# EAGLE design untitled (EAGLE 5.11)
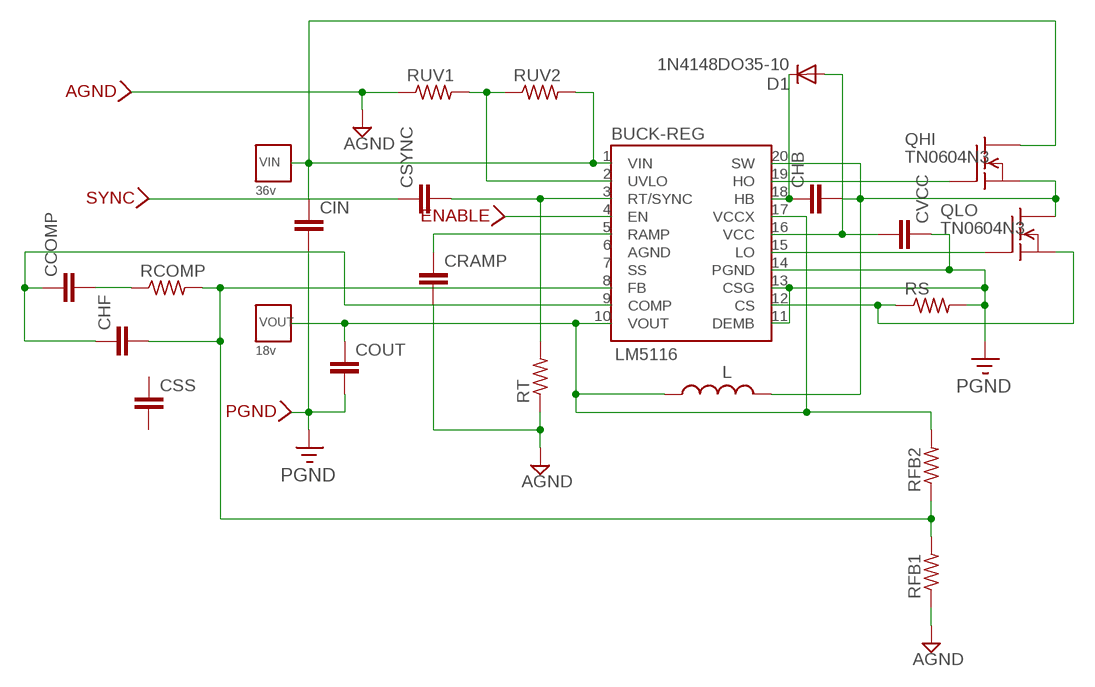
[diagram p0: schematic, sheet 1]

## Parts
AGND  WIREPAD-SMD-SMALL-NAMED  [WIREPAD-SMD-SMALL]
BUCK-REG  LM5116  [TSSOP20-POWERPAD]
CCOMP  C-EUC0805  [C0805]
CHB  C-EUC0805  [C0805]
CHF  C-EUC0805  [C0805]
CIN  C-EUC0805  [C0805]
COUT  C-EUC0805  [C0805]
CRAMP  C-EUC0805  [C0805]
CSS  C-EUC0805  [C0805]
CSYNC  C-EUC0805  [C0805]
CVCC  C-EUC0805  [C0805]
D1  1N4148DO35-10  [DO35-10]
ENABLE  WIREPAD-SMD-SMALL-NAMED  [WIREPAD-SMD-SMALL]
L  INDUCTOR  [INDUCTOR-ABRACON-1306S]
PGND  WIREPAD-SMD-SMALL-NAMED  [WIREPAD-SMD-SMALL]
QHI  TN0604N3  [TO-92]
QLO  TN0604N3  [TO-92]
RCOMP  R-US_R0805  [R0805]
RFB1  R-US_R0805  [R0805]
RFB2  R-US_R0805  [R0805]
RS  R-US_R0805  [R0805]
RT  R-US_R0805  [R0805]
RUV1  R-US_R0805  [R0805]
RUV2  R-US_R0805  [R0805]
SYNC  WIREPAD-SMD-SMALL-NAMED  [WIREPAD-SMD-SMALL]
VIN  36v  WIREPAD-SMD5X5MM  [WIREPAD-SMD-5X5MM]
VOUT  18v  WIREPAD-SMD5X5MM  [WIREPAD-SMD-5X5MM]

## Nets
AGND: AGND.1 CRAMP.2 RFB1.1 RT.1 RUV1.1
N$1: CSYNC.1 SYNC.1
N$2: BUCK-REG.5(RAMP) CRAMP.1
N$3: BUCK-REG.8(FB) CHF.2 RCOMP.2 RFB1.2 RFB2.1
N$4: BUCK-REG.1(VIN) CIN.1 QHI.3(D) RUV2.2 VIN.1(P)
N$5: BUCK-REG.2(UVLO) RUV1.2 RUV2.1
N$6: BUCK-REG.3(RT/SYNC) CSYNC.2 RT.2
N$7: BUCK-REG.4(EN) ENABLE.1
N$8: BUCK-REG.9(COMP) CCOMP.1 CHF.1
N$9: BUCK-REG.10(VOUT) BUCK-REG.17(VCCX) COUT.1 L.1 RFB2.2 VOUT.1(P)
N$10: CCOMP.2 RCOMP.1
N$11: BUCK-REG.19(HO) QHI.2(G)
N$12: BUCK-REG.20(SW) CHB.2 L.2 QHI.1(S) QLO.3(D)
N$13: BUCK-REG.18(HB) CHB.1 D1.C
N$14: BUCK-REG.12(CS) QLO.1(S) RS.1
N$15: BUCK-REG.16(VCC) CVCC.2 D1.A
N$16: BUCK-REG.15(LO) QLO.2(G)
PGND: BUCK-REG.11(DEMB) BUCK-REG.13(CSG) BUCK-REG.14(PGND) CIN.2 COUT.2 CVCC.1 PGND.1 RS.2
Unconnected: BUCK-REG.6(AGND) BUCK-REG.7(SS) CSS.1 CSS.2

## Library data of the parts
AGND ENABLE PGND SYNC = trl:WIREPAD-SMD-SMALL-NAMED
BUCK-REG = trl:LM5116
CCOMP CHB CHF CIN COUT CRAMP CSS CSYNC CVCC = rcl:C-EU: CAPACITOR, European symbol
D1 = diode:1N4148: DIODE
L = trl:INDUCTOR
QHI QLO = transistor-fet:TN0604N3: N-Channel Enhancement MOSFET 40V; 4A; 0,75Ohm
RCOMP RFB1 RFB2 RS RT RUV1 RUV2 = resistor:R-US_: RESISTOR, American symbol
VIN VOUT = trl:WIREPAD-SMD

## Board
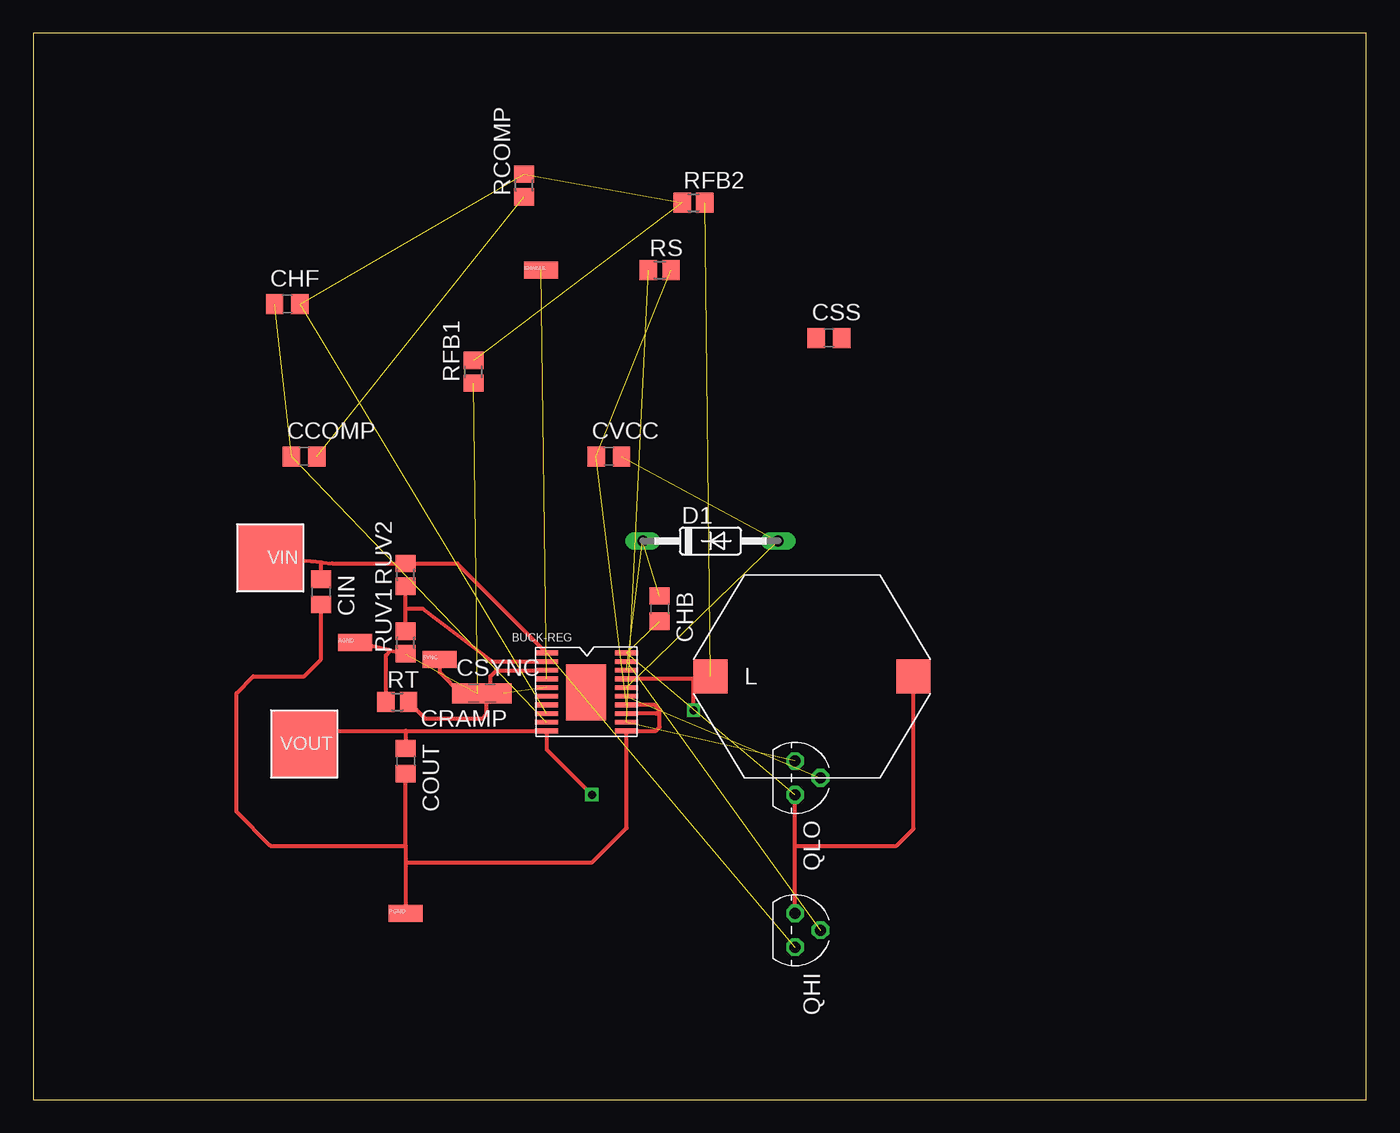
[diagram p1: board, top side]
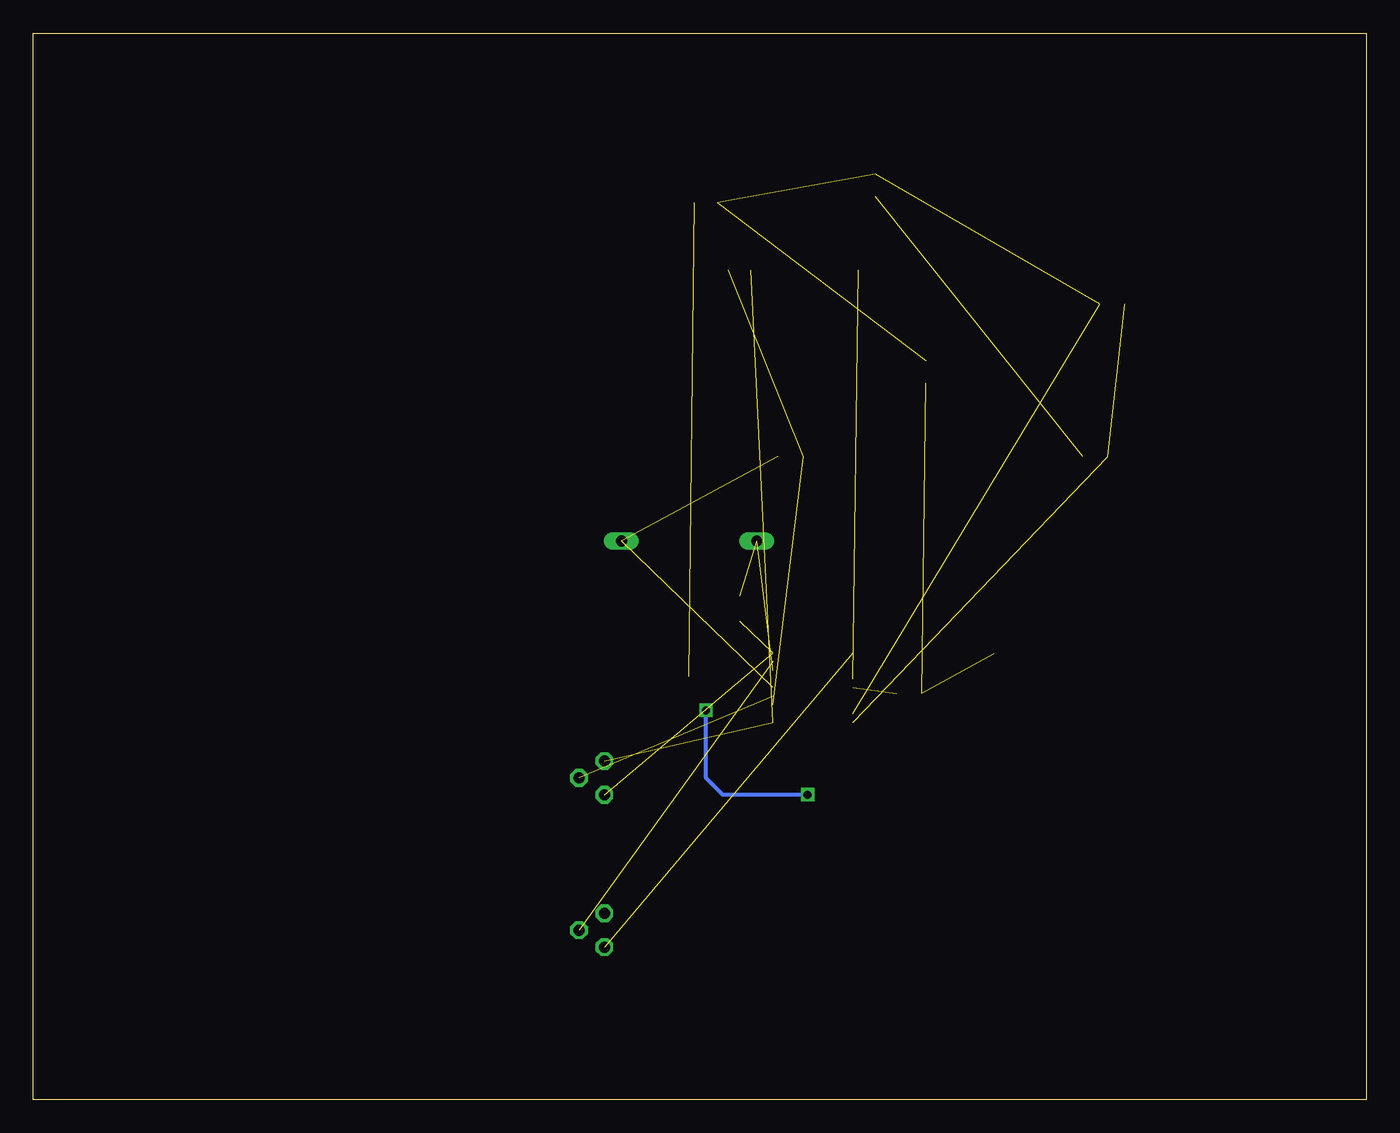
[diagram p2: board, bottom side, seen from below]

Size 100 x 80 mm. Coordinates in mm from the lower left corner, seen from the top.
Outline: 0,0 100,0 100,80 0,80 0,0
Copper layers (1*16): Top 0.035mm / dielectric 1.5mm / Bottom 0.035mm
Design rules "default": minimum track width 10mil, minimum drill 0.6mm, track to track 8mil, track to pad 8mil, pad to pad 8mil, via to via 8mil, smd to smd 8mil, copper to edge 40mil, drill to drill 8mil, minimum pad ring 10mil, minimum via ring 8mil, stop-mask expansion 4mil, vias tented up to drill 0mil, thermal gap 10mil

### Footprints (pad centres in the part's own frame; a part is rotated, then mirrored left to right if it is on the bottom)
WIREPAD-SMD-SMALL = smd 2.54 x 1.27: 1 0,0
TSSOP20-POWERPAD = smd 1.75 x 0.35: 1 9.3,10.65; 2 9.3,10; 3 9.3,9.35; 4 9.3,8.7; 5 9.3,8.05; 6 9.3,7.4; 7 9.3,6.75; 8 9.3,6.1; 9 9.3,5.45; 10 9.3,4.8; 11 15.3,4.8; 12 15.3,5.45; 13 15.3,6.1; 14 15.3,6.75; 15 15.3,7.4; 16 15.3,8.05; 17 15.3,8.7; 18 15.3,9.35; 19 15.3,10; 20 15.3,10.65 | smd 3 x 4.2: PAD 12.25,7.7
C0805 = smd 1.3 x 1.5: 1 -0.95,0; 2 0.95,0
DO35-10 = drill 0.813 long: A 5.08,0; C -5.08,0
INDUCTOR-ABRACON-1306S = smd 2.54 x 2.54: 1 0,0; 2 15.24,0
TO-92 = drill 0.813 octagon: 1 -1.27,0; 2 0,1.905; 3 1.27,0
R0805 = smd 1.3 x 1.5: 1 -0.85,0; 2 0.85,0
WIREPAD-SMD-5X5MM = smd 5 x 5: 1 0,0

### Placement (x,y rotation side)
AGND  24.13,34.29 0 top
BUCK-REG  29.21,22.86 0 top
CCOMP  20.32,48.26 0 top
CHB  46.99,36.83 270 top
CHF  19.05,59.69 0 top
CIN  21.59,38.1 270 top
COUT  27.94,25.4 270 top
CRAMP  34.29,30.48 180 top
CSS  59.69,57.15 0 top
CSYNC  33.02,30.48 0 top
CVCC  43.18,48.26 0 top
D1  50.8,41.91 0 top
ENABLE  38.1,62.23 0 top
L  50.8,31.75 0 top
PGND  27.94,13.97 0 top
QHI  57.15,12.7 270 top
QLO  57.15,24.13 270 top
RCOMP  36.83,68.58 90 top
RFB1  33.02,54.61 90 top
RFB2  49.53,67.31 0 top
RS  46.99,62.23 0 top
RT  27.3,29.84 0 top
RUV1  27.94,34.29 90 top
RUV2  27.94,39.37 90 top
SYNC  30.48,33.02 0 top
VIN  17.78,40.64 90 top
VOUT  20.32,26.67 90 top

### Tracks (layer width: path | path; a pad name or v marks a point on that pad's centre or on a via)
AGND  (2 unrouted)
  Top 0.305: 26.82,33.69 AGND.1 | 26.82,33.69 RUV1.1 | RT.1 26.45,33.33 26.82,33.69
N$1
  Top 0.305: SYNC.1 30.48,32.07 CSYNC.1
N$2  (1 unrouted)
N$3  (4 unrouted)
N$4  (1 unrouted)
  Top 0.305: 21.67,40.29 VIN.1 | 21.67,40.29 22.44,40.22 RUV2.2 31.8,40.22 BUCK-REG.1 | CIN.1 21.59,40.21 21.67,40.29
N$5
  Top 0.305: RUV1.2 27.94,36.83 | 27.94,36.83 RUV2.1 | BUCK-REG.2 34.45,32.86 29.21,36.83 27.94,36.83
N$6
  Top 0.305: BUCK-REG.3 34.75,32.21 34.29,31.75 34.29,30.8 CSYNC.2 33.97,28.89 33.66,28.57 29.43,28.57 RT.2
N$7  (1 unrouted)
N$8  (2 unrouted)
N$9  (via drill 0.6)  (1 unrouted)
  Top 0.305: 27.94,27.66 21.31,27.66 VOUT.1 | 27.94,27.66 BUCK-REG.10 38.51,26.26 v41.91,22.86 | 27.94,27.66 COUT.1 | 49.53,31.56 BUCK-REG.17 | 49.53,31.56 50.61,31.56 L.1 | v49.53,29.21 49.53,31.56
  Bottom 0.305: v41.91,22.86 48.26,22.86 49.53,24.13 v49.53,29.21
N$10  (1 unrouted)
N$11  (1 unrouted)
N$12  (2 unrouted)
  Top 0.305: QHI.1 57.15,19.05 | 57.15,19.05 QLO.3 | L.2 66.04,20.32 64.77,19.05 57.15,19.05
N$13  (2 unrouted)
N$14  (2 unrouted)
N$15  (2 unrouted)
N$16  (1 unrouted)
PGND  (2 unrouted)
  Top 0.305: 27.94,19.05 27.94,17.78 | 27.94,19.05 COUT.2 | 27.94,17.78 41.91,17.78 44.51,20.38 BUCK-REG.11 46.71,27.66 46.99,27.94 46.99,29.21 | 27.94,17.78 PGND.1 | BUCK-REG.13 46.74,28.96 46.99,29.21 | BUCK-REG.14 46.59,29.61 46.99,29.21 | CIN.2 21.59,33.02 20.32,31.75 16.51,31.75 15.24,30.48 15.24,21.59 17.78,19.05 27.94,19.05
